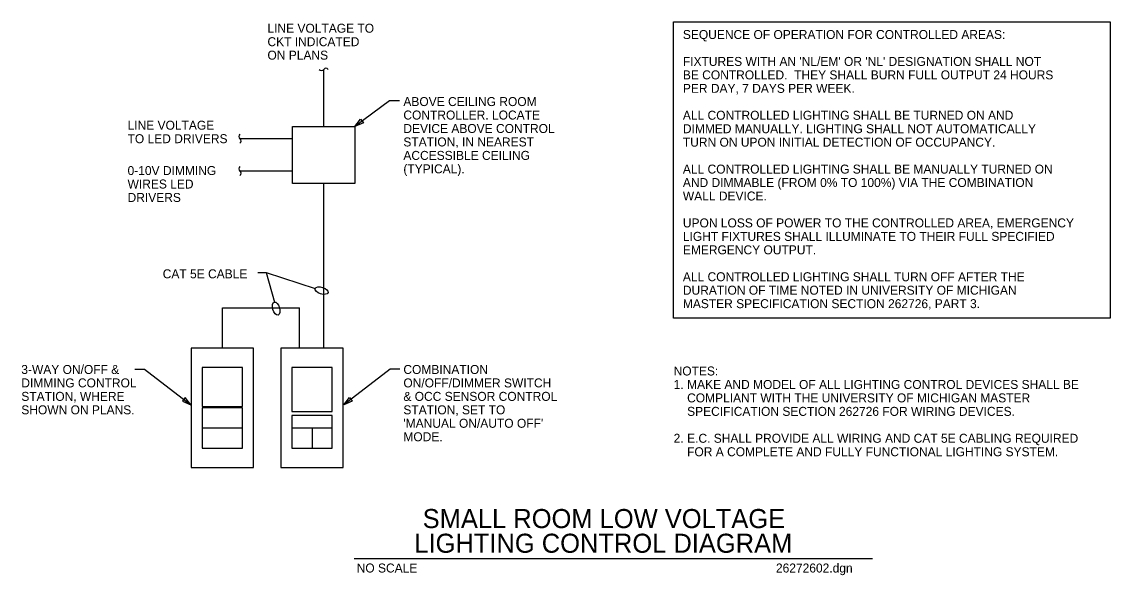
# Model space of a CAD drawing. Extents: x 10017.2 to 10098.1, y 10051.3 to 10092.4.
import ezdxf

# ---------------------------------------------------------------- set-up
doc = ezdxf.new("R2010")
doc.units = 0
for name, color, linetype in [('G-ANNO-CELL', 7, 'Continuous'), ('G-ANNO-TEXT', 7, 'Continuous'), ('G-DETL-LINE', 7, 'Continuous'), ('Level 3', 7, 'Continuous')]:
    doc.layers.add(name, color=color, linetype=linetype)

msp = doc.modelspace()

# ---------------------------------------------------------------- linework, layer by layer
at = {"layer": 'G-ANNO-CELL'}
msp.add_line((10041.898, 10052.523), (10080.422, 10052.523), dxfattribs=at)
at = {"layer": 'G-ANNO-TEXT'}
msp.add_line((10035.339, 10073.769), (10038.995, 10072.59), dxfattribs=at)
for points in [[(10065.642, 10092.412), (10098.104, 10092.412), (10098.104, 10070.386), (10065.642, 10070.386)], [(10042.573, 10084.915), (10041.943, 10084.641), (10042.37, 10085.18)], [(10029.116, 10064.224), (10029.744, 10063.944), (10029.321, 10064.486)], [(10041.751, 10064.224), (10041.123, 10063.944), (10041.546, 10064.486)]]:
    msp.add_lwpolyline(points, close=True, dxfattribs=at)
for points in [[(10045.259, 10086.539), (10044.53, 10086.539), (10041.943, 10084.641)], [(10034.737, 10073.769), (10035.339, 10073.769), (10035.959, 10071.581)], [(10025.575, 10066.602), (10026.304, 10066.602), (10029.744, 10063.944)], [(10045.292, 10066.602), (10044.563, 10066.602), (10041.123, 10063.944)]]:
    msp.add_lwpolyline(points, dxfattribs=at)
for centre, major_axis in [((10039.471, 10072.437), (0.476, -0.153)), ((10036.095, 10071.1), (0.136, -0.481))]:
    msp.add_ellipse(centre, major_axis=major_axis, ratio=0.5, dxfattribs=at)
at = {"layer": 'G-DETL-LINE'}
for p, q in [((10039.626, 10084.641), (10039.626, 10088.877)), ((10037.31, 10083.718), (10033.396, 10083.718)), ((10037.31, 10081.321), (10033.396, 10081.321)), ((10039.626, 10068.157), (10039.626, 10080.397)), ((10032.093, 10068.157), (10032.093, 10071.163)), ((10032.093, 10071.163), (10037.817, 10071.163)), ((10037.817, 10068.157), (10037.817, 10071.163)), ((10033.593, 10062.219), (10030.593, 10062.219)), ((10040.265, 10062.219), (10037.265, 10062.219)), ((10038.765, 10062.219), (10038.765, 10060.719))]:
    msp.add_line(p, q, dxfattribs=at)
for points in [[(10037.31, 10084.641), (10041.943, 10084.641), (10041.943, 10080.397), (10037.31, 10080.397)], [(10034.409, 10068.157), (10029.777, 10068.157), (10029.777, 10059.281), (10034.409, 10059.281)], [(10041.082, 10068.157), (10036.449, 10068.157), (10036.449, 10059.281), (10041.082, 10059.281)], [(10033.593, 10066.719), (10030.593, 10066.719), (10030.593, 10063.832), (10033.593, 10063.832)], [(10040.265, 10066.719), (10037.265, 10066.719), (10037.265, 10063.44), (10040.265, 10063.44)], [(10033.593, 10063.719), (10030.593, 10063.719), (10030.593, 10060.719), (10033.593, 10060.719)], [(10040.265, 10063.157), (10037.265, 10063.157), (10037.265, 10060.719), (10040.265, 10060.719)]]:
    msp.add_lwpolyline(points, close=True, dxfattribs=at)
for centre, start, end in [((10039.46, 10089.002), 216.8699, 323.1301), ((10039.793, 10088.752), 36.8699, 143.1301), ((10033.521, 10083.885), 126.8699, 233.1301), ((10033.271, 10083.551), 306.8699, 53.1301), ((10033.521, 10081.487), 126.8699, 233.1301), ((10033.271, 10081.154), 306.8699, 53.1301)]:
    msp.add_arc(centre, 0.208, start, end, dxfattribs=at)

# ---------------------------------------------------------------- texts
at = {"layer": 'G-ANNO-CELL'}
for s, height, p in [('SMALL ROOM LOW VOLTAGE', 1.41667, (10046.985, 10054.789)), ('LIGHTING CONTROL DIAGRAM', 1.41667, (10046.365, 10052.955)), ('NO SCALE', 0.6667, (10042.078, 10051.488))]:
    msp.add_text(s, height=height, dxfattribs=at).set_placement(p)
at = {"layer": 'G-ANNO-TEXT'}
for s, height, p in [('LINE VOLTAGE TO ', 0.66667, (10035.445, 10091.598)), ('SEQUENCE OF OPERATION FOR CONTROLLED AREAS:', 0.66667, (10066.33, 10091.132)), ('CKT INDICATED ', 0.66667, (10035.445, 10090.598)), ('ON PLANS', 0.6667, (10035.445, 10089.598)), ("FIXTURES WITH AN 'NL/EM' OR 'NL' DESIGNATION SHALL NOT ", 0.66667, (10066.33, 10089.132)), ('BE CONTROLLED.  THEY SHALL BURN FULL OUTPUT 24 HOURS ', 0.66667, (10066.33, 10088.132)), ('PER DAY, 7 DAYS PER WEEK.', 0.66667, (10066.33, 10087.132)), ('ABOVE CEILING ROOM ', 0.66667, (10045.55, 10086.149)), ('LINE VOLTAGE ', 0.66667, (10025.044, 10084.391)), ('CONTROLLER. LOCATE ', 0.66667, (10045.55, 10085.149)), ('ALL CONTROLLED LIGHTING SHALL BE TURNED ON AND ', 0.66667, (10066.33, 10085.132)), ('DEVICE ABOVE CONTROL ', 0.66667, (10045.55, 10084.149)), ('DIMMED MANUALLY. LIGHTING SHALL NOT AUTOMATICALLY ', 0.66667, (10066.33, 10084.132)), ('TO LED DRIVERS', 0.66667, (10025.044, 10083.391)), ('STATION, IN NEAREST ', 0.66667, (10045.55, 10083.149)), ('TURN ON UPON INITIAL DETECTION OF OCCUPANCY.', 0.66667, (10066.33, 10083.132)), ('ACCESSIBLE CEILING ', 0.66667, (10045.55, 10082.149)), ('(TYPICAL).', 0.6667, (10045.55, 10081.149)), ('0-10V DIMMING ', 0.66667, (10025.044, 10081.023)), ('ALL CONTROLLED LIGHTING SHALL BE MANUALLY TURNED ON ', 0.66667, (10066.33, 10081.132)), ('WIRES LED ', 0.6667, (10025.044, 10080.023)), ('AND DIMMABLE (FROM 0% TO 100%) VIA THE COMBINATION ', 0.66667, (10066.33, 10080.132)), ('DRIVERS ', 0.6667, (10025.044, 10079.023)), ('WALL DEVICE.', 0.66667, (10066.33, 10079.132)), ('UPON LOSS OF POWER TO THE CONTROLLED AREA, EMERGENCY ', 0.66667, (10066.33, 10077.132)), ('LIGHT FIXTURES SHALL ILLUMINATE TO THEIR FULL SPECIFIED ', 0.66667, (10066.33, 10076.132)), ('EMERGENCY OUTPUT.', 0.66667, (10066.33, 10075.132)), ('CAT 5E CABLE', 0.66667, (10027.657, 10073.348)), ('ALL CONTROLLED LIGHTING SHALL TURN OFF AFTER THE ', 0.66667, (10066.33, 10073.132)), ('DURATION OF TIME NOTED IN UNIVERSITY OF MICHIGAN ', 0.66667, (10066.33, 10072.132)), ('MASTER SPECIFICATION SECTION 262726, PART 3.', 0.66667, (10066.33, 10071.132)), ('3-WAY ON/OFF & ', 0.66667, (10017.143, 10066.243)), ('COMBINATION ', 0.66667, (10045.55, 10066.243)), ('NOTES:', 0.6667, (10065.642, 10066.129)), ('DIMMING CONTROL ', 0.66667, (10017.143, 10065.243)), ('ON/OFF/DIMMER SWITCH ', 0.66667, (10045.55, 10065.243)), ('1.', 0.6667, (10065.642, 10065.129)), ('MAKE AND MODEL OF ALL LIGHTING CONTROL DEVICES SHALL BE ', 0.66667, (10066.645, 10065.129)), ('STATION, WHERE ', 0.66667, (10017.143, 10064.243)), ('& OCC SENSOR CONTROL ', 0.66667, (10045.55, 10064.243)), ('COMPLIANT WITH THE UNIVERSITY OF MICHIGAN MASTER ', 0.66667, (10066.645, 10064.129)), ('SHOWN ON PLANS.', 0.66667, (10017.143, 10063.243)), ('STATION, SET TO ', 0.66667, (10045.55, 10063.243)), ('SPECIFICATION SECTION 262726 FOR WIRING DEVICES.', 0.66667, (10066.645, 10063.129)), ("'MANUAL ON/AUTO OFF' ", 0.66667, (10045.55, 10062.243)), ('MODE.', 0.6667, (10045.55, 10061.243)), ('2.', 0.6667, (10065.642, 10061.129)), ('E.C. SHALL PROVIDE ALL WIRING AND CAT 5E CABLING REQUIRED ', 0.66667, (10066.645, 10061.129)), ('FOR A COMPLETE AND FULLY FUNCTIONAL LIGHTING SYSTEM.', 0.66667, (10066.645, 10060.129))]:
    msp.add_text(s, height=height, dxfattribs=at).set_placement(p)
at = {"layer": 'Level 3'}
msp.add_text('26272602.dgn', height=0.66667, dxfattribs=at).set_placement((10073.251, 10051.488))

doc.saveas('drawing.dxf')
